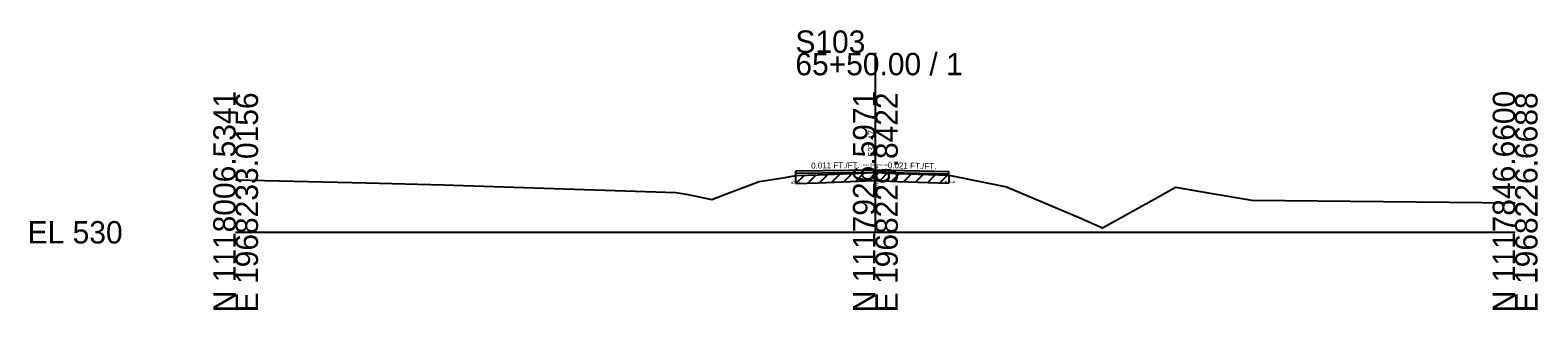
# Model space of a CAD drawing. Extents: x -26 to 163, y -10 to 24018.
# Drawn here: x -25.7 to 162.8, y 13490.3 to 13525.3 of the extents above; entities that cross this region are included whole.
import ezdxf

# ---------------------------------------------------------------- set-up
doc = ezdxf.new("R2010")
doc.units = 0
for name, color, linetype in [('RD_GPK_XS_Cell', 7, 'Continuous'), ('RD_XS_ExGround', 7, 'Continuous'), ('RD_XS_ExPaveRet', 7, 'Continuous'), ('RD_XS_Misc_Line', 7, 'Continuous'), ('RD_XS_PaveOvlay_CP', 7, 'Continuous'), ('RD_XS_TX_Elev_EX', 7, 'Continuous'), ('RD_XS_TX_ExEOP', 7, 'Continuous'), ('RD_XS_TX_Notes', 7, 'Continuous'), ('RD_XS_TX_Profile', 7, 'Continuous'), ('RD_XS_TX_Slope', 7, 'Continuous')]:
    doc.layers.add(name, color=color, linetype=linetype)

msp = doc.modelspace()

# ---------------------------------------------------------------- linework, layer by layer
at = {"layer": 'RD_GPK_XS_Cell'}
for p, q in [((80, 13500), (80, 13522.43)), ((0, 13500), (80, 13500)), ((80, 13500), (160, 13500))]:
    msp.add_line(p, q, dxfattribs=at)
at = {"layer": 'RD_XS_ExGround'}
msp.add_lwpolyline([(0, 13506.55), (16.38, 13506.19), (26.01, 13505.93), (38.53, 13505.52), (55.09, 13504.98), (56.34, 13504.75), (59.53, 13504.1), (61.07, 13504.69), (65.47, 13506.33), (68.7, 13506.86), (70.04, 13507.08), (72.86, 13507.2), (79.89, 13507.48), (82.8, 13507.37), (89.2, 13507.15), (94.37, 13506.12), (96.38, 13505.69), (105.48, 13501.84), (108.41, 13500.55), (115.34, 13504.4), (117.53, 13505.64), (121.62, 13504.94), (127.08, 13504.01), (160, 13503.68)], dxfattribs=at)
at = {"layer": 'RD_XS_ExPaveRet'}
for p, q in [((70.04, 13506.08), (71.09, 13507.12)), ((70.04, 13506.08), (70.04, 13507.08)), ((71.54, 13506.14), (72.59, 13507.19)), ((73.04, 13506.21), (74.09, 13507.25)), ((74.54, 13506.27), (75.59, 13507.31)), ((76.04, 13506.32), (77.09, 13507.37)), ((77.54, 13506.38), (78.59, 13507.42)), ((79.04, 13506.44), (80.07, 13507.47)), ((80.54, 13506.45), (81.51, 13507.42)), ((82.04, 13506.4), (83.01, 13507.36)), ((83.54, 13506.34), (84.51, 13507.31)), ((85.04, 13506.29), (86.01, 13507.26)), ((86.54, 13506.24), (87.51, 13507.21)), ((88.04, 13506.19), (89.01, 13507.15)), ((89.2, 13507.15), (89.2, 13506.15)), ((70.04, 13506.08), (72.86, 13506.2)), ((72.86, 13506.2), (79.89, 13506.48)), ((79.89, 13506.48), (82.8, 13506.37)), ((82.8, 13506.37), (89.2, 13506.15))]:
    msp.add_line(p, q, dxfattribs=at)
at = {"layer": 'RD_XS_Misc_Line'}
msp.add_line((79.89, 13507.48), (79.89, 13504.48), dxfattribs=at)
at = {"layer": 'RD_XS_PaveOvlay_CP'}
for p, q in [((70.04, 13507.69), (80, 13507.8)), ((70.04, 13507.08), (70.04, 13507.69)), ((80, 13507.47), (70.04, 13507.36)), ((80, 13507.8), (89.2, 13507.61)), ((89.2, 13507.28), (80, 13507.47)), ((89.2, 13507.15), (89.2, 13507.61))]:
    msp.add_line(p, q, dxfattribs=at)

# ---------------------------------------------------------------- texts
at = {"layer": 'RD_GPK_XS_Cell'}
for s, p in [('S103', (70, 13522.43)), ('65+50.00 / 1', (70, 13519.63)), ('EL 530', (-26, 13498.6))]:
    msp.add_text(s, height=2.8, dxfattribs=at).set_placement(p)
for s, p in [('N 1118006.5341', (0, 13490)), ('E 1968233.0156', (2.8, 13490)), ('N 1117926.5971', (80, 13490)), ('E 1968229.8422', (82.8, 13490)), ('N 1117846.6600', (160, 13490)), ('E 1968226.6688', (162.8, 13490))]:
    msp.add_text(s, height=2.8, rotation=90, dxfattribs=at).set_placement(p)
at = {"layer": 'RD_XS_TX_Elev_EX'}
msp.add_text('537.47', height=0.8, rotation=90, dxfattribs=at).set_placement((79.9, 13509.47))
at = {"layer": 'RD_XS_TX_ExEOP'}
for s, p in [('EOP-L', (69.99, 13507.69)), ('EOP-R', (89.15, 13507.61))]:
    msp.add_text(s, height=0.1, rotation=270, dxfattribs=at).set_placement(p)
at = {"layer": 'RD_XS_TX_Notes'}
for s, p in [('Elev. @CL = 537.80', (78.47, 13508.3)), (' dE= 0.33', (79.29, 13506.47)), (' dE= 0.61', (69.34, 13506.08)), (' dE= 0.46', (88.49, 13506.15))]:
    msp.add_text(s, height=0.25, dxfattribs=at).set_placement(p)
msp.add_text(' Min. Distance @CP = -0.01', height=0.25, rotation=270, dxfattribs=at).set_placement((80.14, 13508.56))
at = {"layer": 'RD_XS_TX_Profile'}
msp.add_text('CL', height=0.25, dxfattribs=at).set_placement((79.77, 13507.8))
at = {"layer": 'RD_XS_TX_Slope'}
for s, rotation, p in [('0.011 FT./FT.', 0.6388, (71.97, 13507.96)), ('0.021 FT./FT.', 358.8084, (81.55, 13508.01))]:
    msp.add_text(s, height=0.75, rotation=rotation, dxfattribs=at).set_placement(p)

doc.saveas('drawing.dxf')
